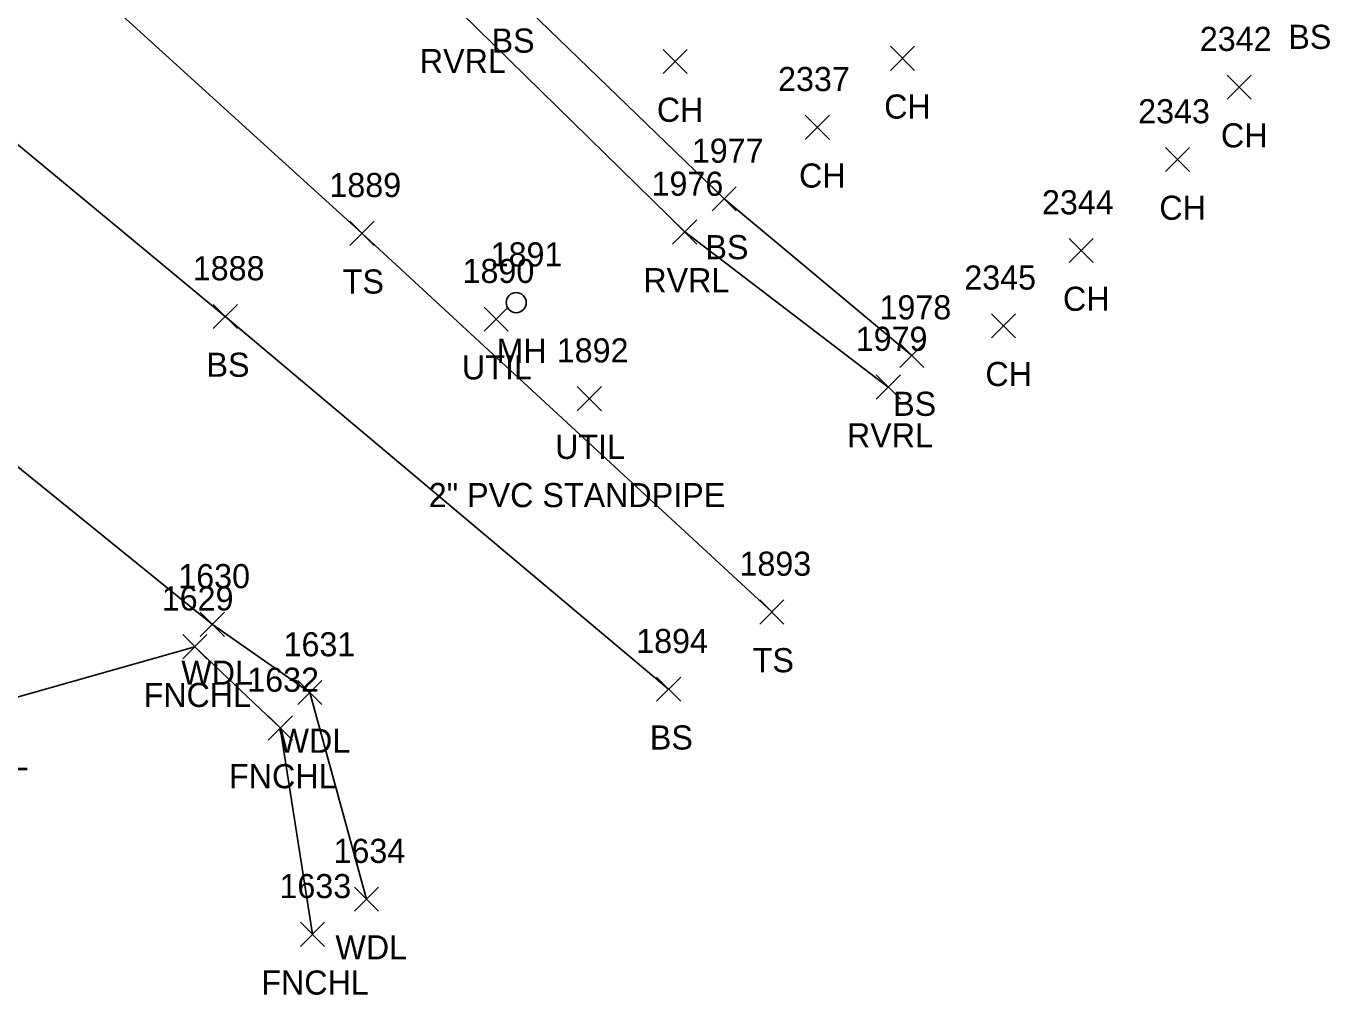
# Model space of a CAD drawing. Extents: x 1647133 to 1649138, y 411736 to 414924.
# Drawn here: x 1648877.6 to 1648985.7, y 411982.9 to 412063.3 of the extents above; entities that cross this region are included whole.
import ezdxf

# ---------------------------------------------------------------- set-up
doc = ezdxf.new("R2010")
doc.units = 0
for name, color, linetype in [('L_A', 7, 'Continuous'), ('L_I', 7, 'Continuous'), ('L_TIC', 7, 'Continuous'), ('LAWA', 7, 'Continuous'), ('LAWE', 7, 'Continuous'), ('LELB', 7, 'Continuous'), ('LFNC', 7, 'Continuous'), ('U_A', 7, 'Continuous'), ('U_C', 7, 'Continuous'), ('U_I', 7, 'Continuous'), ('UDEFAULT', 7, 'Continuous'), ('UUMH', 7, 'Continuous')]:
    doc.layers.add(name, color=color, linetype=linetype)

msp = doc.modelspace()

# ---------------------------------------------------------------- linework, layer by layer
at = {"layer": 'L_TIC'}
for points in [[(1648930.4, 412059.31), (1648932.4, 412061.31)], [(1648932.4, 412059.31), (1648930.4, 412061.31)], [(1648949.24, 412059.58), (1648951.24, 412061.58)], [(1648951.24, 412059.58), (1648949.24, 412061.58)], [(1648977.16, 412057.19), (1648979.16, 412059.19)], [(1648979.16, 412057.19), (1648977.16, 412059.19)], [(1648942.19, 412053.86), (1648944.19, 412055.86)], [(1648944.19, 412053.86), (1648942.19, 412055.86)], [(1648972.05, 412051.19), (1648974.05, 412053.19)], [(1648974.05, 412051.19), (1648972.05, 412053.19)], [(1648934.47, 412047.92), (1648936.47, 412049.92)], [(1648936.47, 412047.92), (1648934.47, 412049.92)], [(1648904.43, 412045.07), (1648906.43, 412047.07)], [(1648906.43, 412045.07), (1648904.43, 412047.07)], [(1648931.19, 412045.18), (1648933.19, 412047.18)], [(1648933.19, 412045.18), (1648931.19, 412047.18)], [(1648964.07, 412043.64), (1648966.07, 412045.64)], [(1648966.07, 412043.64), (1648964.07, 412045.64)], [(1648893.1, 412038.17), (1648895.1, 412040.17)], [(1648895.1, 412038.17), (1648893.1, 412040.17)], [(1648957.63, 412037.4), (1648959.63, 412039.4)], [(1648959.63, 412037.4), (1648957.63, 412039.4)], [(1648950.03, 412034.93), (1648952.03, 412036.93)], [(1648952.03, 412034.93), (1648950.03, 412036.93)], [(1648948.07, 412032.32), (1648950.07, 412034.32)], [(1648950.07, 412032.32), (1648948.07, 412034.32)], [(1648938.42, 412013.67), (1648940.42, 412015.67)], [(1648940.42, 412013.67), (1648938.42, 412015.67)], [(1648892.03, 412012.64), (1648894.03, 412014.64)], [(1648894.03, 412012.64), (1648892.03, 412014.64)], [(1648890.58, 412010.79), (1648892.58, 412012.79)], [(1648892.58, 412010.79), (1648890.58, 412012.79)], [(1648900.11, 412006.99), (1648902.11, 412008.99)], [(1648902.11, 412006.99), (1648900.11, 412008.99)], [(1648929.86, 412007.26), (1648931.86, 412009.26)], [(1648931.86, 412007.26), (1648929.86, 412009.26)], [(1648897.66, 412004.05), (1648899.66, 412006.05)], [(1648899.66, 412004.05), (1648897.66, 412006.05)], [(1648904.81, 411989.86), (1648906.81, 411991.86)], [(1648906.81, 411989.86), (1648904.81, 411991.86)], [(1648900.33, 411986.94), (1648902.33, 411988.94)], [(1648902.33, 411986.94), (1648900.33, 411988.94)]]:
    msp.add_lwpolyline(points, dxfattribs=at)
at = {"layer": 'LAWA'}
msp.add_lwpolyline([(1648847.55, 412073.48), (1648845.96, 412067.03), (1648849.4, 412053.94), (1648872.68, 412030.1), (1648893.03, 412013.64), (1648901.11, 412007.99), (1648905.81, 411990.86)], dxfattribs=at)
at = {"layer": 'LAWE'}
msp.add_lwpolyline([(1648837.13, 412133.1), (1648849.11, 412130.58), (1648858.55, 412123.43), (1648865.22, 412116.65), (1648885.08, 412098.31), (1648895.74, 412085.32), (1648904.97, 412074.68), (1648913.66, 412064.35), (1648932.19, 412046.18), (1648949.07, 412033.32)], dxfattribs=at)
at = {"layer": 'LELB'}
for points in [[(1648875.31, 412117.61), (1648882.6, 412109.86), (1648888.6, 412101.42), (1648898.39, 412087.96), (1648908.25, 412075.41), (1648917.74, 412066.05), (1648935.47, 412048.92), (1648951.03, 412035.93)], [(1648870.71, 412072.87), (1648871.76, 412057.66), (1648894.1, 412039.17), (1648930.86, 412008.26)], [(1648870.71, 412072.87), (1648878.04, 412070.97), (1648905.43, 412046.07), (1648939.42, 412014.67)]]:
    msp.add_lwpolyline(points, dxfattribs=at)
at = {"layer": 'LFNC'}
msp.add_lwpolyline([(1648859.51, 411993.77), (1648873.1, 412006.55), (1648891.58, 412011.79), (1648898.66, 412005.05), (1648901.33, 411987.94)], dxfattribs=at)
at = {"layer": 'UDEFAULT'}
for points in [[(1648915.55, 412037.95), (1648917.55, 412039.95)], [(1648917.55, 412037.95), (1648915.55, 412039.95)], [(1648923.28, 412031.36), (1648925.28, 412033.36)], [(1648925.28, 412031.36), (1648923.28, 412033.36)]]:
    msp.add_lwpolyline(points, dxfattribs=at)
at = {"layer": 'UUMH'}
for p, q in [((1648918.22, 412040.32), (1648918.22, 412040.32)), ((1648919.06, 412040.32), (1648919.06, 412040.32))]:
    msp.add_line(p, q, dxfattribs=at)
msp.add_circle((1648918.22, 412040.32), 0.833, dxfattribs=at)

# ---------------------------------------------------------------- texts
at = {"layer": 'L_A'}
for s, p in [('BS', (1648916.18, 412061.05)), ('BS', (1648982.24, 412061.36)), ('RVRL', (1648910.23, 412059.35)), ('CH', (1648948.73, 412055.58)), ('CH', (1648929.88, 412055.31)), ('CH', (1648976.65, 412053.19)), ('CH', (1648941.67, 412049.86)), ('CH', (1648971.54, 412047.19)), ('BS', (1648933.91, 412043.92)), ('TS', (1648903.84, 412041.07)), ('RVRL', (1648928.76, 412041.18)), ('CH', (1648963.55, 412039.64)), ('BS', (1648892.54, 412034.17)), ('CH', (1648957.12, 412033.4)), ('BS', (1648949.47, 412030.93)), ('RVRL', (1648945.64, 412028.32)), ('TS', (1648937.83, 412009.67)), ('WDL', (1648890.45, 412008.64)), ('FNCHL', (1648887.32, 412006.79)), ('WDL', (1648898.52, 412002.99)), ('BS', (1648929.3, 412003.26)), ('FNCHL', (1648868.85, 412001.55)), ('FNCHL', (1648894.41, 412000.05)), ('WDL', (1648903.23, 411985.86)), ('FNCHL', (1648897.08, 411982.94))]:
    msp.add_text(s, height=2, dxfattribs=at).set_placement(p)
at = {"layer": 'L_I'}
for s, p in [('2342', (1648974.9, 412061.19)), ('2337', (1648939.93, 412057.86)), ('2343', (1648969.79, 412055.19)), ('1977', (1648932.78, 412051.92)), ('1976', (1648929.44, 412049.18)), ('1889', (1648902.73, 412049.07)), ('2344', (1648961.81, 412047.64)), ('1888', (1648891.4, 412042.17)), ('2345', (1648955.37, 412041.4)), ('1978', (1648948.34, 412038.93)), ('1979', (1648946.37, 412036.32)), ('1893', (1648936.73, 412017.67)), ('1630', (1648890.2, 412016.64)), ('1629', (1648888.83, 412014.79)), ('1894', (1648928.17, 412011.26)), ('1631', (1648898.93, 412010.99)), ('1632', (1648895.92, 412008.05)), ('1634', (1648903.07, 411993.86)), ('1633', (1648898.59, 411990.94))]:
    msp.add_text(s, height=2, dxfattribs=at).set_placement(p)
at = {"layer": 'U_A'}
for s, p in [('MH', (1648916.59, 412035.32)), ('UTIL', (1648913.72, 412033.95)), ('UTIL', (1648921.44, 412027.36))]:
    msp.add_text(s, height=2, dxfattribs=at).set_placement(p)
at = {"layer": 'U_C'}
msp.add_text('2" PVC STANDPIPE', height=2, dxfattribs=at).set_placement((1648910.97, 412023.36))
at = {"layer": 'U_I'}
for s, p in [('1891', (1648916.1, 412043.32)), ('1890', (1648913.77, 412041.95)), ('1892', (1648921.58, 412035.36))]:
    msp.add_text(s, height=2, dxfattribs=at).set_placement(p)

doc.saveas('drawing.dxf')
